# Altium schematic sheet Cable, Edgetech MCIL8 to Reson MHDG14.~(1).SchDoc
size B; Organization: Monterey Bay Aquarium Research Institute; Address1: 7700 Sandholdt Rd; Address2: Moss Landing, CA 95039-9644; CompanyName: MBARI
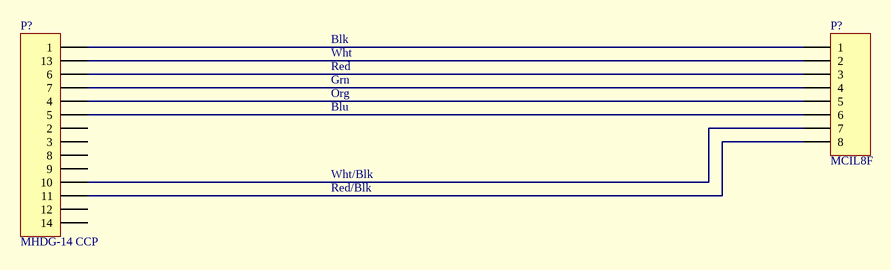
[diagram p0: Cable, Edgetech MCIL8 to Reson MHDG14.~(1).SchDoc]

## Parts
(Parts that share a designator on the sheet are numbered #1, #2 ... from top to bottom, then left to right.)
P?#1  MHDG-14 CCP  [HDR1X14]
P?#2  MCIL8F  [HDR1X8]

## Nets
NetP?#1_1: P?#1.1 P?#2.1
NetP?#1_4: P?#1.4 P?#2.5
NetP?#1_5: P?#1.5 P?#2.6
NetP?#1_6: P?#1.6 P?#2.3
NetP?#1_7: P?#1.7 P?#2.4
NetP?#1_10: P?#1.10 P?#2.7
NetP?#1_11: P?#1.11 P?#2.8
NetP?#1_13: P?#1.13 P?#2.2

Not connected (* = marked no-connect by the designer): P?#1 2 3 8 9 12 14

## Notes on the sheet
- Blk
- Wht
- Red
- Grn
- Org
- Blu
- Wht/Blk
- Red/Blk

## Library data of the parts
P?#1 = Header 14: Header, 14-Pin
P?#2 = Header 8: Header, 8-Pin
